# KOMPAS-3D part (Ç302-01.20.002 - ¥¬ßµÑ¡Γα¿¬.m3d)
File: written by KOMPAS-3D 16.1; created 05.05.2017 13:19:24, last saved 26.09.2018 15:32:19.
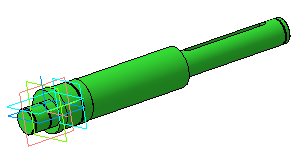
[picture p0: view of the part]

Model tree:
1. Эскиз:1
2. Операция выдавливания:1
     Расстояние 1 = 144.5
3. Эскиз:4
4. Операция выдавливания:3
     Расстояние 1 = 29
5. Смещенная плоскость:1
     Расстояние = 2.3
6. Эскиз:7
7. Вырезать элемент выдавливания:4
     Расстояние 1 = 1.4
8. Фаска:1
     Угол = 45; Длина 1 = 0.5; Длина 2 = 0.5
9. Массив по сетке:1  (with: Вырезать элемент выдавливания:4, Смещенная плоскость:1, Эскиз:7)  (2 pattern instances)
     Шаг 1 = 16.1; Угол раствора = 90; Номер 1 = 1
10. Эскиз:8
11. Операция вращения:1
     Угол 1 = 360
12. Фаска:2
     Угол = 45; Длина 1 = 1; Длина 2 = 1
13. Смещенная плоскость:2
     Расстояние = 8.5
14. Эскиз:9
15. Вырезать элемент выдавливания:5
     Расстояние 2 = 4; Расстояние 1 = 4
16. Эскиз:10
17. Вырезать элемент выдавливания:6
     Расстояние 1 = 136.5; На расстояние 1 = 8
18. Эскиз:11
19. Вырезать элемент выдавливания:7
     Расстояние 1 = 106.5; На расстояние 1 = 30
20. Фаска:3
     Угол = 45; Длина 1 = 0.5; Длина 2 = 0.5
21. Смещенная плоскость:3
     Расстояние = 18
22. Эскиз:12
23. Вырезать элемент выдавливания:8  (labels: А302-01.20.002; Сталь 40Х  ГОСТ 4543-71)
     Расстояние 2 = 1.85; Расстояние 1 = 55; На расстояние 1 = 8

Expressions: 25/2; 23.5/2; 112+1.3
